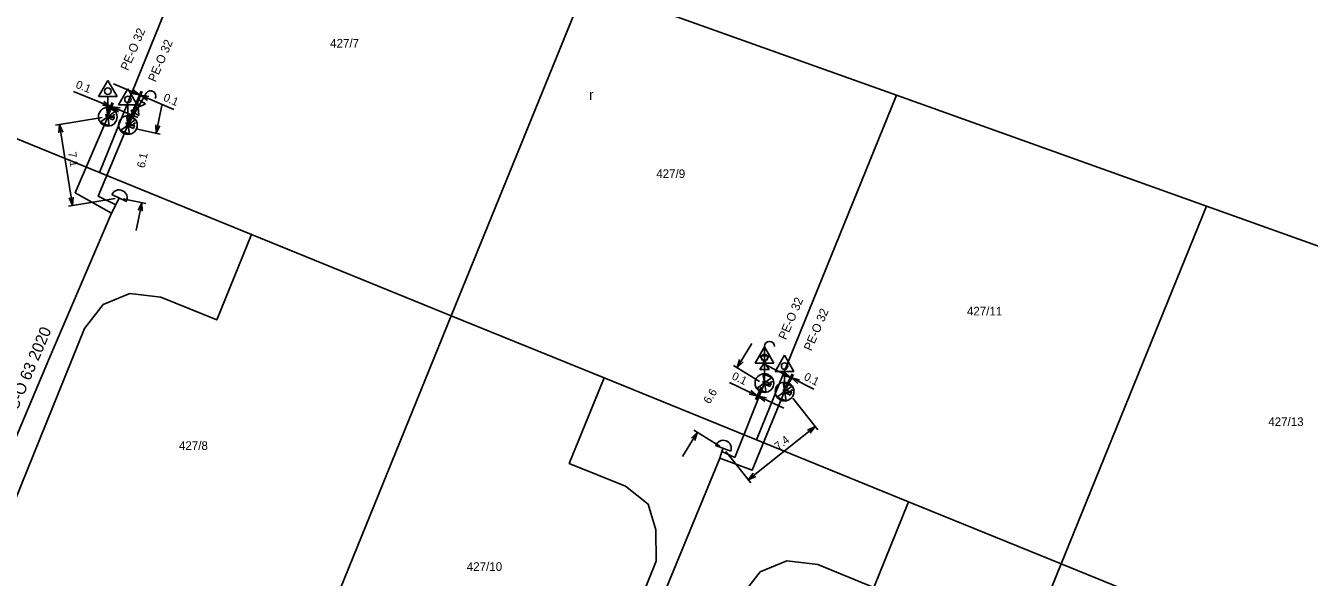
# Model space of a CAD drawing. Extents: x -836615 to -835459, y -1070675 to -1070205.
# Drawn here: x -836392.7 to -836281.4, y -1070379.5 to -1070331.7 of the extents above; entities that cross this region are included whole.
import ezdxf

# ---------------------------------------------------------------- set-up
doc = ezdxf.new("R2010")
doc.units = 0
for name, color, linetype in [('Budovy_kody', 7, 'Continuous'), ('OstPloch_kody', 7, 'Continuous'), ('RuianPar_popis', 7, 'Continuous'), ('Vrstva 1', 7, 'Continuous'), ('Vrstva 21', 7, 'Continuous'), ('Vrstva 24', 7, 'Continuous'), ('Vrstva 31', 7, 'Continuous'), ('Vrstva 36', 7, 'Continuous'), ('Vrstva 37', 7, 'Continuous')]:
    doc.layers.add(name, color=color, linetype=linetype)

msp = doc.modelspace()

# ---------------------------------------------------------------- linework, layer by layer
at = {"layer": 'Budovy_kody'}
msp.add_lwpolyline([(-836403.24, -1070306.2), (-836374.99, -1070316.69), (-836386.28, -1070344.47), (-836399.48, -1070339.1), (-836416.81, -1070332.05)], close=True, dxfattribs=at)
for points in [[(-836374.99, -1070316.69), (-836344.08, -1070328.14), (-836355.76, -1070356.88), (-836373.08, -1070349.83), (-836386.28, -1070344.47)], [(-836342.51, -1070362.26), (-836329.31, -1070367.63), (-836317.16, -1070337.75), (-836344.08, -1070328.14)], [(-836317.16, -1070337.75), (-836290.27, -1070347.37), (-836302.87, -1070378.38), (-836316.11, -1070373), (-836329.31, -1070367.63)], [(-836290.49, -1070383.42), (-836277.29, -1070388.78), (-836264.23, -1070356.67), (-836290.27, -1070347.37)], [(-836373.08, -1070349.83), (-836376.1, -1070357.24), (-836380.96, -1070355.27), (-836383.64, -1070354.94), (-836385.94, -1070355.91), (-836387.56, -1070357.98), (-836398.1, -1070383.91), (-836389.8, -1070388.59), (-836382.53, -1070391.55), (-836381.43, -1070388.86), (-836370.56, -1070393.28), (-836355.76, -1070356.88), (-836342.51, -1070362.26), (-836345.53, -1070369.67), (-836340.66, -1070371.65), (-836338.69, -1070373.21), (-836338.03, -1070375.41), (-836338, -1070378.13), (-836348.92, -1070405.21), (-836361.26, -1070400.19), (-836361.24, -1070397.07), (-836370.56, -1070393.28)], [(-836316.11, -1070373), (-836319.13, -1070380.41), (-836323.99, -1070378.43), (-836326.67, -1070378.11), (-836328.97, -1070379.07), (-836330.59, -1070381.15), (-836341.51, -1070408.22), (-836318.77, -1070417.47), (-836302.87, -1070378.38), (-836290.49, -1070383.42), (-836293.5, -1070390.83), (-836288.73, -1070392.77), (-836286.67, -1070394.36), (-836285.68, -1070396.69), (-836285.97, -1070399.29), (-836295.88, -1070426.77), (-836318.77, -1070417.47)]]:
    msp.add_lwpolyline(points, dxfattribs=at)
at = {"layer": 'Vrstva 1'}
for p, q in [((-836385.04, -1070336.77), (-836382.79, -1070337.73)), ((-836388.52, -1070337.43), (-836385.3, -1070338.73)), ((-836383.79, -1070340.08), (-836382.65, -1070337.41)), ((-836383.7, -1070340.12), (-836382.56, -1070337.45)), ((-836379.81, -1070339.01), (-836382.7, -1070337.77)), ((-836385.55, -1070339.34), (-836385.17, -1070338.41)), ((-836385.45, -1070339.38), (-836385.07, -1070338.45)), ((-836382.93, -1070339.69), (-836385.2, -1070338.77)), ((-836380.86, -1070338.66), (-836381.36, -1070341.06)), ((-836386.03, -1070339.71), (-836390.08, -1070340.36)), ((-836389.73, -1070340.3), (-836388.62, -1070347.31)), ((-836382.98, -1070340.72), (-836381.01, -1070341.13)), ((-836384.92, -1070346.72), (-836388.97, -1070347.37)), ((-836384.23, -1070346.74), (-836382.26, -1070347.15)), ((-836383.1, -1070349.48), (-836382.61, -1070347.08)), ((-836329.7, -1070359.27), (-836330.98, -1070361.36)), ((-836329.03, -1070362.56), (-836331.28, -1070361.18)), ((-836328.54, -1070361.11), (-836326.35, -1070362.22)), ((-836326.82, -1070363.15), (-836326.2, -1070361.9)), ((-836326.73, -1070363.19), (-836326.1, -1070361.95)), ((-836324.33, -1070363.24), (-836326.26, -1070362.26)), ((-836331.65, -1070362.66), (-836329.23, -1070363.8)), ((-836328.88, -1070363.06), (-836329.38, -1070364.12)), ((-836328.79, -1070363.1), (-836329.29, -1070364.16)), ((-836326.92, -1070364.89), (-836329.14, -1070363.85)), ((-836326.15, -1070364.02), (-836323.99, -1070366.75)), ((-836335.71, -1070369.07), (-836334.43, -1070366.98)), ((-836332.48, -1070368.18), (-836334.73, -1070366.8)), ((-836330.02, -1070371.09), (-836324.21, -1070366.48)), ((-836331.96, -1070368.63), (-836329.8, -1070371.36))]:
    msp.add_line(p, q, dxfattribs=at)
for points in [[(-836383.36, -1070337.3), (-836382.79, -1070337.73), (-836383.5, -1070337.62)], [(-836382.12, -1070338.21), (-836382.7, -1070337.77), (-836381.98, -1070337.89)], [(-836385.89, -1070338.31), (-836385.3, -1070338.73), (-836386.02, -1070338.63)], [(-836384.62, -1070339.2), (-836385.2, -1070338.77), (-836384.49, -1070338.87)], [(-836389.8, -1070341.02), (-836389.73, -1070340.3), (-836389.45, -1070340.97)], [(-836381.04, -1070340.41), (-836381.36, -1070341.06), (-836381.38, -1070340.34)], [(-836388.56, -1070346.59), (-836388.62, -1070347.31), (-836388.9, -1070346.65)], [(-836382.92, -1070347.73), (-836382.61, -1070347.08), (-836382.58, -1070347.8)], [(-836330.46, -1070360.86), (-836330.98, -1070361.36), (-836330.76, -1070360.67)], [(-836326.9, -1070361.75), (-836326.35, -1070362.22), (-836327.06, -1070362.06)], [(-836325.71, -1070362.73), (-836326.26, -1070362.26), (-836325.56, -1070362.42)], [(-836329.79, -1070363.35), (-836329.23, -1070363.8), (-836329.94, -1070363.66)], [(-836328.58, -1070364.3), (-836329.14, -1070363.85), (-836328.43, -1070363.99)], [(-836334.94, -1070367.49), (-836334.43, -1070366.98), (-836334.64, -1070367.67)], [(-836324.86, -1070366.78), (-836324.21, -1070366.48), (-836324.65, -1070367.05)], [(-836329.36, -1070370.79), (-836330.02, -1070371.09), (-836329.58, -1070370.52)]]:
    msp.add_lwpolyline(points, dxfattribs=at)
at = {"layer": 'Vrstva 21'}
for p, q in [((-836386.36, -1070337.89), (-836385.55, -1070336.48)), ((-836384.74, -1070337.89), (-836385.55, -1070336.48)), ((-836386.36, -1070337.89), (-836384.74, -1070337.89)), ((-836385.55, -1070337.89), (-836385.55, -1070339.63)), ((-836384.61, -1070338.61), (-836383.8, -1070337.2)), ((-836382.99, -1070338.61), (-836383.8, -1070337.2)), ((-836382.21, -1070337.6), (-836383.8, -1070340.35)), ((-836384.89, -1070339.16), (-836386.21, -1070340.1)), ((-836384.89, -1070339.16), (-836385.67, -1070338.83)), ((-836385.43, -1070340.43), (-836385.67, -1070338.83)), ((-836384.61, -1070338.61), (-836382.99, -1070338.61)), ((-836383.8, -1070338.61), (-836383.8, -1070340.35)), ((-836382.28, -1070338.51), (-836383.54, -1070339.12)), ((-836382.86, -1070339.52), (-836383.54, -1070339.12)), ((-836382.28, -1070338.51), (-836382.96, -1070338.11)), ((-836382.96, -1070338.11), (-836382.86, -1070339.52)), ((-836385.43, -1070340.43), (-836386.21, -1070340.1)), ((-836383.14, -1070339.88), (-836384.46, -1070340.82)), ((-836383.14, -1070339.88), (-836383.93, -1070339.55)), ((-836383.67, -1070341.15), (-836383.93, -1070339.55)), ((-836383.67, -1070341.15), (-836384.46, -1070340.82)), ((-836385.2, -1070346.36), (-836383.94, -1070346.98)), ((-836329.42, -1070360.97), (-836328.61, -1070359.56)), ((-836328.21, -1070360.35), (-836329.01, -1070360.35)), ((-836329.01, -1070360.35), (-836328.21, -1070361.52)), ((-836328.21, -1070360.35), (-836329.01, -1070361.52)), ((-836328.61, -1070359.53), (-836328.61, -1070362.71)), ((-836327.8, -1070360.97), (-836328.61, -1070359.56)), ((-836327.67, -1070361.7), (-836326.86, -1070360.29)), ((-836326.05, -1070361.7), (-836326.86, -1070360.29)), ((-836329.42, -1070360.97), (-836327.8, -1070360.97)), ((-836328.61, -1070360.97), (-836328.61, -1070362.71)), ((-836327.96, -1070362.23), (-836329.26, -1070363.19)), ((-836328.21, -1070361.52), (-836329.01, -1070361.52)), ((-836327.96, -1070362.23), (-836328.75, -1070361.91)), ((-836328.47, -1070363.51), (-836328.75, -1070361.91)), ((-836327.67, -1070361.7), (-836326.05, -1070361.7)), ((-836326.86, -1070361.7), (-836326.86, -1070363.44)), ((-836328.47, -1070363.51), (-836329.26, -1070363.19)), ((-836326.2, -1070362.96), (-836327.52, -1070363.92)), ((-836326.2, -1070362.96), (-836326.99, -1070362.64)), ((-836326.73, -1070364.24), (-836326.99, -1070362.64)), ((-836326.73, -1070364.24), (-836327.52, -1070363.92)), ((-836332.84, -1070368.12), (-836331.52, -1070368.6))]:
    msp.add_line(p, q, dxfattribs=at)
for centre, radius in [((-836385.55, -1070337.42), 0.282), ((-836383.8, -1070338.14), 0.282), ((-836385.55, -1070339.63), 0.812), ((-836383.8, -1070340.35), 0.812), ((-836328.61, -1070360.5), 0.282), ((-836326.86, -1070361.23), 0.282), ((-836328.61, -1070362.71), 0.812), ((-836326.86, -1070363.44), 0.812)]:
    msp.add_circle(centre, radius, dxfattribs=at)
for centre, radius, start, end in [((-836381.83, -1070337.82), 0.436, 329.9162, 149.9162), ((-836382.76, -1070337.28), 0.635, 329.9162247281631, 329.91622742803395), ((-836384.57, -1070346.67), 0.699, 333.7832, 153.7832), ((-836328.17, -1070359.53), 0.436, 0, 180), ((-836329.25, -1070359.53), 0.635, 0, 2.699870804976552e-06), ((-836332.18, -1070368.36), 0.699, 339.9628, 159.9628)]:
    msp.add_arc(centre, radius, start, end, dxfattribs=at)
at = {"layer": 'Vrstva 24'}
for points in [[(-836385.22, -1070347.99), (-836388.39, -1070346.22), (-836385.55, -1070339.63)], [(-836383.8, -1070340.35), (-836386.37, -1070346.52), (-836384.86, -1070347.25)], [(-836403.86, -1070392.01), (-836396.28, -1070373.88), (-836390.68, -1070360.73), (-836385.22, -1070347.99), (-836384.86, -1070347.25), (-836384.57, -1070346.67)], [(-836326.86, -1070363.44), (-836329.68, -1070370.26), (-836332.49, -1070369.21)], [(-836332.29, -1070368.63), (-836331.18, -1070369.14), (-836328.61, -1070362.71)], [(-836348.25, -1070407.6), (-836342.69, -1070394.23), (-836339.65, -1070386.61), (-836332.49, -1070369.21), (-836332.29, -1070368.63), (-836332.18, -1070368.36)]]:
    msp.add_lwpolyline(points, dxfattribs=at)
at = {"layer": 'Vrstva 36'}
for p, q in [((-836385.77, -1070339.46), (-836385.65, -1070339.46)), ((-836385.65, -1070339.46), (-836385.65, -1070339.66)), ((-836385.65, -1070339.66), (-836385.05, -1070339.66)), ((-836385.05, -1070339.66), (-836385.05, -1070339.46)), ((-836385.05, -1070339.46), (-836384.92, -1070339.46)), ((-836384, -1070340.2), (-836383.88, -1070340.2)), ((-836383.88, -1070340.2), (-836383.88, -1070340.4)), ((-836383.28, -1070340.4), (-836383.28, -1070340.2)), ((-836383.28, -1070340.2), (-836383.15, -1070340.2)), ((-836383.88, -1070340.4), (-836383.28, -1070340.4)), ((-836328.77, -1070362.6), (-836328.65, -1070362.6)), ((-836328.65, -1070362.6), (-836328.65, -1070362.8)), ((-836328.65, -1070362.8), (-836328.05, -1070362.8)), ((-836328.05, -1070362.8), (-836328.05, -1070362.6)), ((-836328.05, -1070362.6), (-836327.92, -1070362.6)), ((-836327.02, -1070363.32), (-836326.9, -1070363.32)), ((-836326.9, -1070363.32), (-836326.9, -1070363.52)), ((-836326.9, -1070363.52), (-836326.3, -1070363.52)), ((-836326.3, -1070363.52), (-836326.3, -1070363.32)), ((-836326.3, -1070363.32), (-836326.16, -1070363.32))]:
    msp.add_line(p, q, dxfattribs=at)
at = {"layer": 'Vrstva 37'}
for p, q in [((-836385.68, -1070339.66), (-836385.07, -1070339.91)), ((-836383.93, -1070340.4), (-836383.32, -1070340.65)), ((-836328.73, -1070362.74), (-836328.13, -1070363)), ((-836326.98, -1070363.46), (-836326.37, -1070363.75))]:
    msp.add_line(p, q, dxfattribs=at)
for points in [[(-836385.68, -1070339.66), (-836385.59, -1070339.43), (-836384.98, -1070339.68), (-836385.07, -1070339.91)], [(-836383.93, -1070340.4), (-836383.84, -1070340.17), (-836383.23, -1070340.42), (-836383.32, -1070340.65)], [(-836328.73, -1070362.74), (-836328.63, -1070362.51), (-836328.03, -1070362.77), (-836328.13, -1070363)], [(-836326.98, -1070363.46), (-836326.87, -1070363.23), (-836326.26, -1070363.52), (-836326.37, -1070363.75)]]:
    msp.add_lwpolyline(points, dxfattribs=at)

# ---------------------------------------------------------------- texts
at = {"layer": 'OstPloch_kody'}
msp.add_text('r', height=0.9, dxfattribs=at).set_placement((-836343.82, -1070338.18))
at = {"layer": 'RuianPar_popis'}
for s, p in [('427/7', (-836366.27, -1070333.64)), ('427/9', (-836337.99, -1070344.94)), ('427/11', (-836311.05, -1070356.85)), ('427/13', (-836284.92, -1070366.43)), ('427/8', (-836379.38, -1070368.5)), ('427/10', (-836354.42, -1070378.98))]:
    msp.add_text(s, height=0.75, dxfattribs=at).set_placement(p)
at = {"layer": 'Vrstva 1'}
for s, rotation, p in [('0.1', 337.924, (-836388.39, -1070337.1)), ('0.1', 336.854, (-836380.79, -1070338.21)), ('7.1', 278.9978, (-836388.99, -1070342.73)), ('6.1', 78.2697, (-836382.35, -1070344.11)), ('0.1', 334.7768, (-836331.5, -1070362.34)), ('0.1', 333.2814, (-836325.25, -1070362.38)), ('6.6', 58.4551, (-836333.36, -1070364.57)), ('7.4', 38.4306, (-836327.39, -1070368.56))]:
    msp.add_text(s, height=0.7, rotation=rotation, dxfattribs=at).set_placement(p)
at = {"layer": 'Vrstva 31'}
for s, height, rotation, p in [('PE-O 32', 0.75, 66.7877, (-836383.79, -1070335.69)), ('PE-O 32', 0.75, 66.7877, (-836381.41, -1070336.68)), ('PE-O 32', 0.75, 66.7877, (-836326.74, -1070359.01)), ('PE-O 32', 0.75, 66.7877, (-836324.54, -1070359.98)), ('ST PE-RC-O 63 2020', 1, 66.9984, (-836395.47, -1070370.01))]:
    msp.add_text(s, height=height, rotation=rotation, dxfattribs=at).set_placement(p)

doc.saveas('drawing.dxf')
